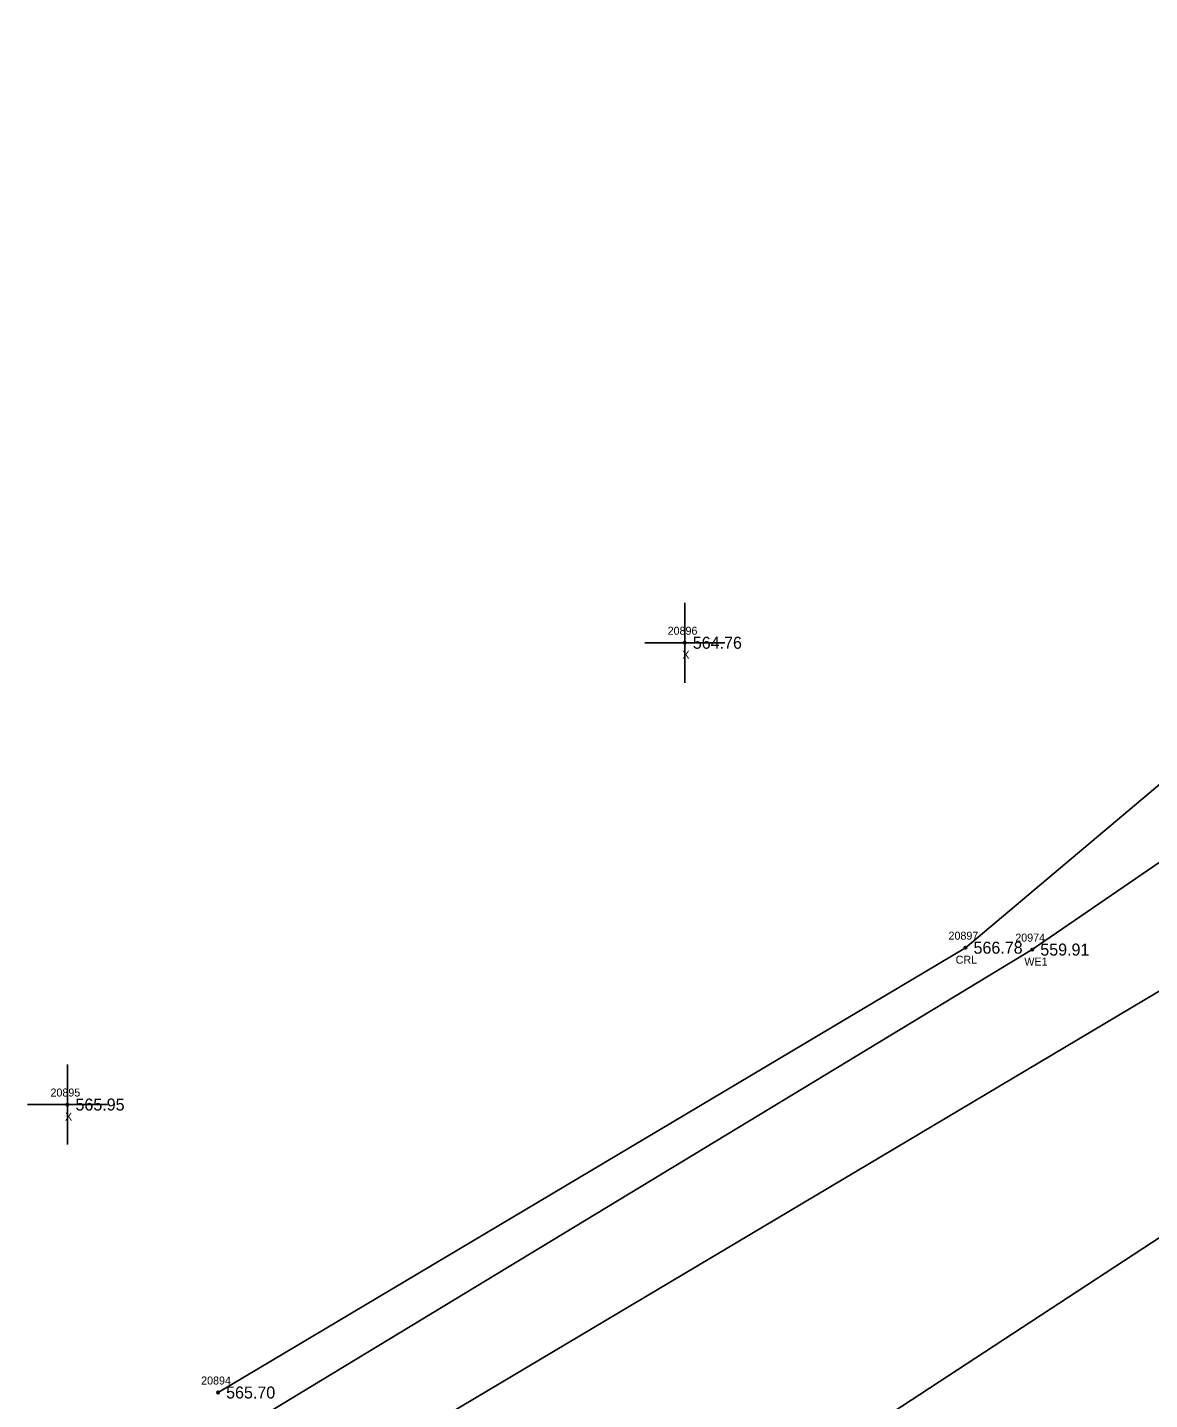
# Model space of a CAD drawing. Extents: x 1695443 to 1696344, y 1087542 to 1090645.
# Drawn here: x 1695456.5 to 1695596.7, y 1088770.4 to 1088941.8 of the extents above; entities that cross this region are included whole.
import ezdxf

# ---------------------------------------------------------------- set-up
doc = ezdxf.new("R2010")
doc.units = 0
for name, color, linetype in [('RD_DTM_BkLn1', 7, 'Continuous'), ('RD_EX_H2O', 7, 'Continuous'), ('RD_EX_H2O_txCode', 7, 'Continuous'), ('RD_EX_Misc', 7, 'Continuous'), ('RD_EX_Misc_txCode', 7, 'Continuous'), ('RD_EX_TX_H2O_ELEV', 7, 'Continuous'), ('RD_EX_TX_Misc_ELEV', 7, 'Continuous'), ('RD_SMD_Locator', 7, 'Continuous')]:
    doc.layers.add(name, color=color, linetype=linetype)

msp = doc.modelspace()

# ---------------------------------------------------------------- linework, layer by layer
at = {"layer": 'RD_DTM_BkLn1'}
msp.add_lwpolyline([(1695477.93, 1088750.04), (1695615.7, 1088831.98), (1695678.81, 1088884.02), (1695727.39, 1088931.9), (1695787.9, 1089007.61), (1695838.8, 1089064.32), (1695878.44, 1089095.49), (1695937, 1089135.88), (1696036.12, 1089170.43), (1696157.88, 1089137.18), (1696204, 1089102.76), (1696222.69, 1089094.08), (1696233.22, 1089076.04), (1696249.95, 1089031.73), (1696253.49, 1088951.92)], dxfattribs=at)
at = {"layer": 'RD_EX_H2O'}
for points in [[(1695466.3, 1088756.42), (1695582.06, 1088826.6), (1695651.04, 1088873.87), (1695702.34, 1088921.12), (1695742.91, 1088967.28), (1695775.02, 1089011.92), (1695840.03, 1089086.93), (1695863.99, 1089105.53), (1695935.01, 1089145.27), (1696036.06, 1089178.39), (1696162.35, 1089145.09), (1696220.48, 1089108.56), (1696243.56, 1089079.86), (1696260.75, 1089035.89), (1696273.81, 1089006.71), (1696286.66, 1088942.65)], [(1695498.69, 1088725.6), (1695608.54, 1088797.54), (1695668.72, 1088841.78), (1695723.76, 1088906.07), (1695797.15, 1088991.78), (1695861.15, 1089050.89), (1695886.72, 1089073.86), (1695948.49, 1089109.39), (1696039, 1089143.17), (1696151.62, 1089114.84), (1696213.01, 1089073.69), (1696220.87, 1089032.47), (1696230.14, 1088992.72), (1696246.9, 1088917.69)], [(1695480.35, 1088771.26), (1695573.72, 1088826.84), (1695643.37, 1088885.49), (1695699.12, 1088929.62), (1695727.71, 1088968.15)]]:
    msp.add_lwpolyline(points, dxfattribs=at)
at = {"layer": 'RD_EX_Misc'}
for p, q in [((1695538.65, 1088859.94), (1695538.65, 1088869.94)), ((1695533.65, 1088864.94), (1695543.65, 1088864.94)), ((1695461.53, 1088802.24), (1695461.53, 1088812.24)), ((1695456.53, 1088807.24), (1695466.53, 1088807.24))]:
    msp.add_line(p, q, dxfattribs=at)
at = {"layer": 'RD_SMD_Locator'}
for centre in [(1695538.65, 1088864.94), (1695573.72, 1088826.84), (1695582.06, 1088826.6), (1695461.53, 1088807.24), (1695480.35, 1088771.26)]:
    msp.add_circle(centre, 0.15, dxfattribs=at)

# ---------------------------------------------------------------- texts
at = {"layer": 'RD_EX_H2O_txCode'}
for s, p in [('20897', (1695571.6, 1088827.84)), ('20974', (1695579.94, 1088827.6)), ('CRL', (1695572.49, 1088824.84)), ('WE1', (1695581.07, 1088824.6)), ('20894', (1695478.23, 1088772.26))]:
    msp.add_text(s, height=1, dxfattribs=at).set_placement(p)
at = {"layer": 'RD_EX_Misc_txCode'}
for s, p in [('20896', (1695536.51, 1088865.94)), ('X', (1695538.34, 1088862.94)), ('20895', (1695459.41, 1088808.24)), ('X', (1695461.22, 1088805.24))]:
    msp.add_text(s, height=1, dxfattribs=at).set_placement(p)
at = {"layer": 'RD_EX_TX_H2O_ELEV'}
for s, p in [('566.78', (1695574.72, 1088826.09)), ('559.91', (1695583.06, 1088825.85)), ('565.70', (1695481.35, 1088770.51))]:
    msp.add_text(s, height=1.5, dxfattribs=at).set_placement(p)
at = {"layer": 'RD_EX_TX_Misc_ELEV'}
for s, p in [('564.76', (1695539.65, 1088864.19)), ('565.95', (1695462.53, 1088806.49))]:
    msp.add_text(s, height=1.5, dxfattribs=at).set_placement(p)

doc.saveas('drawing.dxf')
